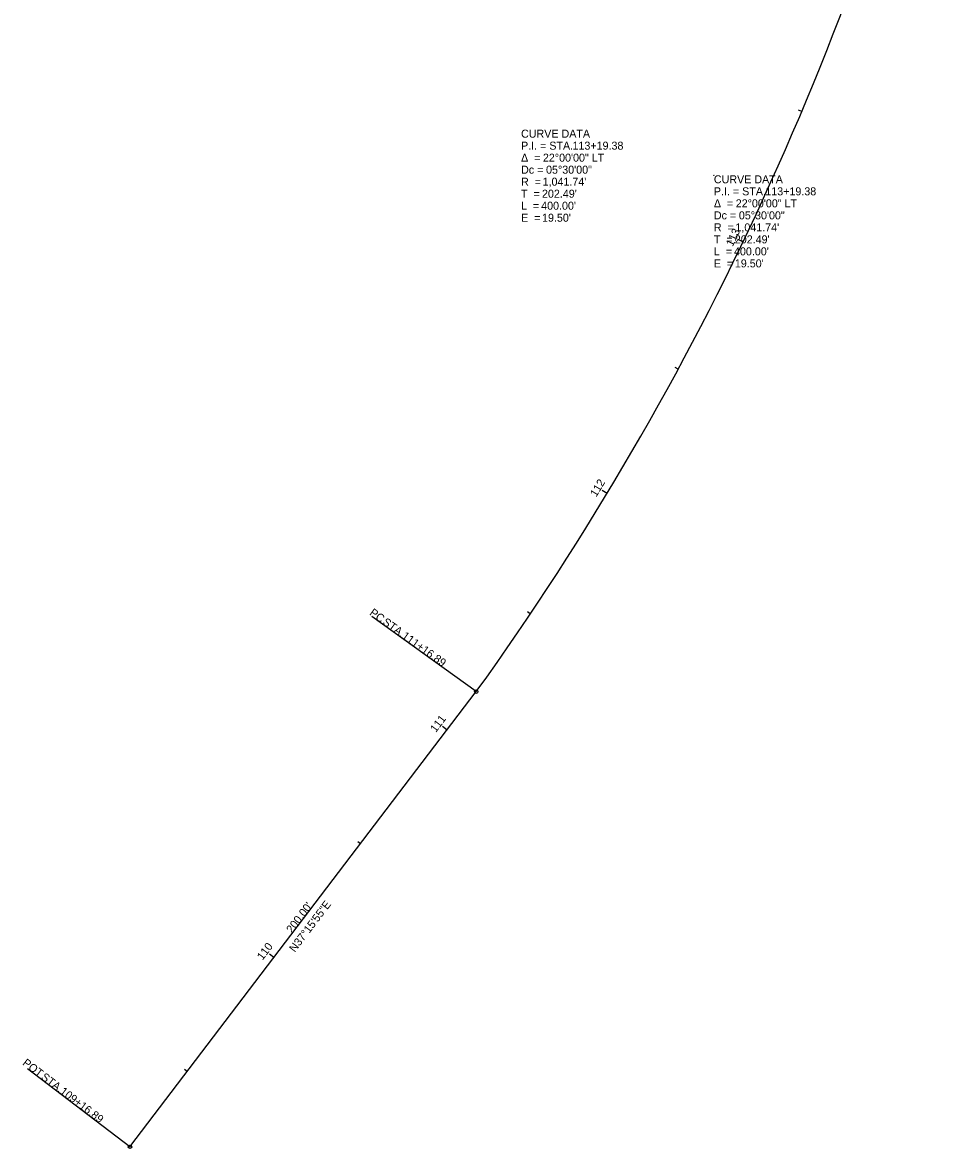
# Model space of a CAD drawing. Extents: x 1832834 to 1833221, y 712492 to 713942.
# Drawn here: x 1832834.2 to 1833159.1, y 712491.9 to 712885.7 of the extents above; entities that cross this region are included whole.
import ezdxf

# ---------------------------------------------------------------- set-up
doc = ezdxf.new("R2010")
doc.units = 0
for name, color, linetype in [('DT_X_Break_Line', 7, 'Continuous'), ('DT_X_Contour_Major', 7, 'Continuous'), ('DT_X_Contour_Minor', 7, 'Continuous'), ('DT_X_Island', 7, 'Continuous'), ('DT_X_Spot_Elev', 7, 'Continuous'), ('DT_X_Terrain_Ground_Line', 7, 'Continuous'), ('DT_X_Void', 7, 'Continuous')]:
    doc.layers.add(name, color=color, linetype=linetype)

msp = doc.modelspace()

# ---------------------------------------------------------------- linework, layer by layer
at = {"layer": 'DT_X_Contour_Minor'}
msp.add_line((1832871.81, 712492.52), (1832992.92, 712651.69), dxfattribs=at)
msp.add_arc((1832147.05, 713259.75), 1041.74, 324.28906, 346.28909, dxfattribs=at)
at = {"layer": 'DT_X_Spot_Elev'}
for p, q in [((1832992.92, 712651.69), (1832956.38, 712677.96)), ((1832871.81, 712492.52), (1832836, 712519.77))]:
    msp.add_line(p, q, dxfattribs=at)
for centre in [(1832992.92, 712651.69), (1832871.81, 712492.52)]:
    msp.add_circle(centre, 0.6, dxfattribs=at)
at = {"layer": 'DT_X_Terrain_Ground_Line'}
msp.add_circle((1833076.01, 712832.26), 0.05, dxfattribs=at)
at = {"layer": 'DT_X_Void'}
for p, q in [((1833106.76, 712854.55), (1833105.65, 712855.02)), ((1833086.21, 712808.98), (1833084.41, 712809.84)), ((1833063.5, 712764.44), (1833062.45, 712765.01)), ((1833038.68, 712721.04), (1833036.97, 712722.07)), ((1833011.81, 712678.88), (1833010.81, 712679.55)), ((1832982.69, 712638.25), (1832981.1, 712639.46)), ((1832952.41, 712598.46), (1832951.46, 712599.18)), ((1832922.14, 712558.66), (1832920.55, 712559.88)), ((1832891.86, 712518.87), (1832890.91, 712519.6))]:
    msp.add_line(p, q, dxfattribs=at)

# ---------------------------------------------------------------- texts
at = {"layer": 'DT_X_Break_Line'}
for s, p in [('CURVE DATA', (1833008.58, 712845.43)), ('P.I. = STA. ', (1833008.58, 712841.23)), ('113+19.38', (1833026.57, 712841.23)), ('Δ  = ', (1833008.58, 712837.03)), ('22°00\'00" LT', (1833016.22, 712837.03)), ('Dc = ', (1833008.58, 712832.83)), ('05°30\'00"', (1833017.32, 712832.83)), ('R  = ', (1833008.58, 712828.63)), ("1,041.74'", (1833016.11, 712828.63)), ('CURVE DATA', (1833076.01, 712829.46)), ('T  = ', (1833008.58, 712824.43)), ("202.49'", (1833015.9, 712824.43)), ('P.I. = STA. ', (1833076.01, 712825.26)), ('113+19.38', (1833094, 712825.26)), ("400.00'", (1833015.61, 712820.23)), ('Δ  = ', (1833076.01, 712821.06)), ('22°00\'00" LT', (1833083.66, 712821.06)), ('L  = ', (1833008.58, 712820.23)), ('Dc = ', (1833076.01, 712816.86)), ('05°30\'00"', (1833084.75, 712816.86)), ('E  = ', (1833008.58, 712816.03)), ("19.50'", (1833015.92, 712816.03)), ('R  = ', (1833076.01, 712812.66)), ("1,041.74'", (1833083.55, 712812.66)), ('T  = ', (1833076.01, 712808.46)), ("202.49'", (1833083.33, 712808.46)), ('L  = ', (1833076.01, 712804.26)), ("400.00'", (1833083.05, 712804.26)), ('E  = ', (1833076.01, 712800.06)), ("19.50'", (1833083.35, 712800.06))]:
    msp.add_text(s, height=2.8, dxfattribs=at).set_placement(p)
at = {"layer": 'DT_X_Contour_Major'}
msp.add_text('N37°15\'55"E', height=2.8, rotation=52.7348, dxfattribs=at).set_placement((1832929.45, 712560.35))
at = {"layer": 'DT_X_Island'}
msp.add_text("200.00'", height=2.8, rotation=52.7348, dxfattribs=at).set_placement((1832928.44, 712567.01))
at = {"layer": 'DT_X_Spot_Elev'}
for s, rotation, p in [('PC', 324.2891, (1832955.35, 712678.74)), (' STA. ', 324.2891, (1832959.08, 712676.06)), ('111+16.89', 324.2891, (1832966.65, 712670.62)), ('POT', 322.7348, (1832833.99, 712521.35)), (' STA. ', 322.7348, (1832839.66, 712517.03)), ('109+16.89', 322.7348, (1832847.08, 712511.39))]:
    msp.add_text(s, height=2.8, rotation=rotation, dxfattribs=at).set_placement(p)
at = {"layer": 'DT_X_Void'}
for s, rotation, p in [('113', 64.3601, (1833082.58, 712807.17)), ('112', 58.8601, (1833034.88, 712719.58)), ('111', 52.7348, (1832978.75, 712637.2)), ('110', 52.7348, (1832918.17, 712557.58))]:
    msp.add_text(s, height=2.8, rotation=rotation, dxfattribs=at).set_placement(p)

doc.saveas('drawing.dxf')
